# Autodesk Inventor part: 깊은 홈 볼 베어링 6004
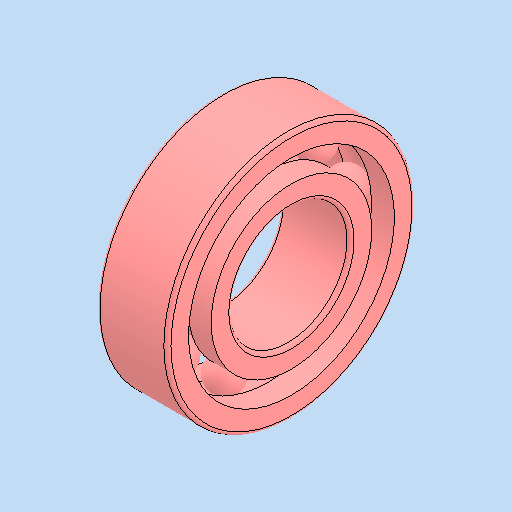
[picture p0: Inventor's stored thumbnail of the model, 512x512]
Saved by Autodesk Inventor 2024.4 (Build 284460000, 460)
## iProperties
Created: 2025-11
Part Number: 깊은 홈 볼 베어링 6004
Material: 강철, 연강
Description: 깊은 그루브 볼 베어링
Document SubType Name: Modeling
Designer: home
Density: 7.85 g/cm^3
Appearance: 기본값
Sending System: Autodesk Inventor 2026
Preprocessor: ST-DEVELOPER v20.1
Author: jhkim
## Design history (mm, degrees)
feature "Solid1"
feature "Solid1:1"
feature "Solid1:2"
feature "Solid1:3"
feature "Solid1:4"
feature "Solid1:5"
feature "Solid1:6"
feature "Solid1:7"
feature "Solid1:8"
feature "Solid1:9"
feature "Solid1:10"
node "솔리드1"
node "솔리드2"
node "솔리드3"
node "솔리드4"
node "솔리드5"
node "솔리드6"
node "솔리드7"
node "솔리드8"
node "솔리드9"
node "솔리드10"
node "솔리드11"
